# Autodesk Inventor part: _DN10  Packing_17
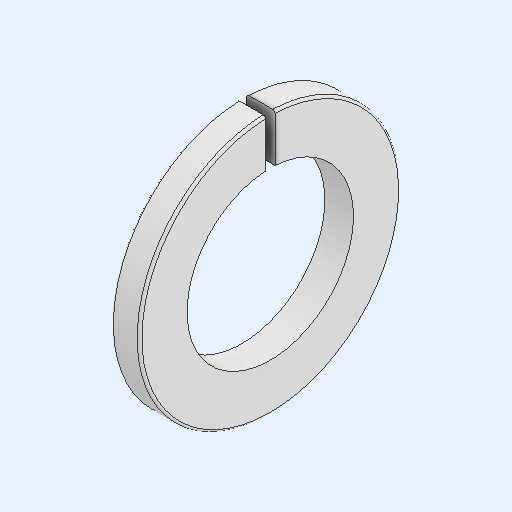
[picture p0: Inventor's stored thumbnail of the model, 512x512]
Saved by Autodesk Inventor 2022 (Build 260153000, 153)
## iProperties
Created: 2021-12
Part Number: _DN10  Packing_17
Material: Generico
Document SubType Name: Modeling
Designer: admin
Density: 1 g/cm^3
Appearance: Default
Author: admin
Revision Number: NONE
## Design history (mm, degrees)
feature "_DN10  Packing"
node "Solido1"
